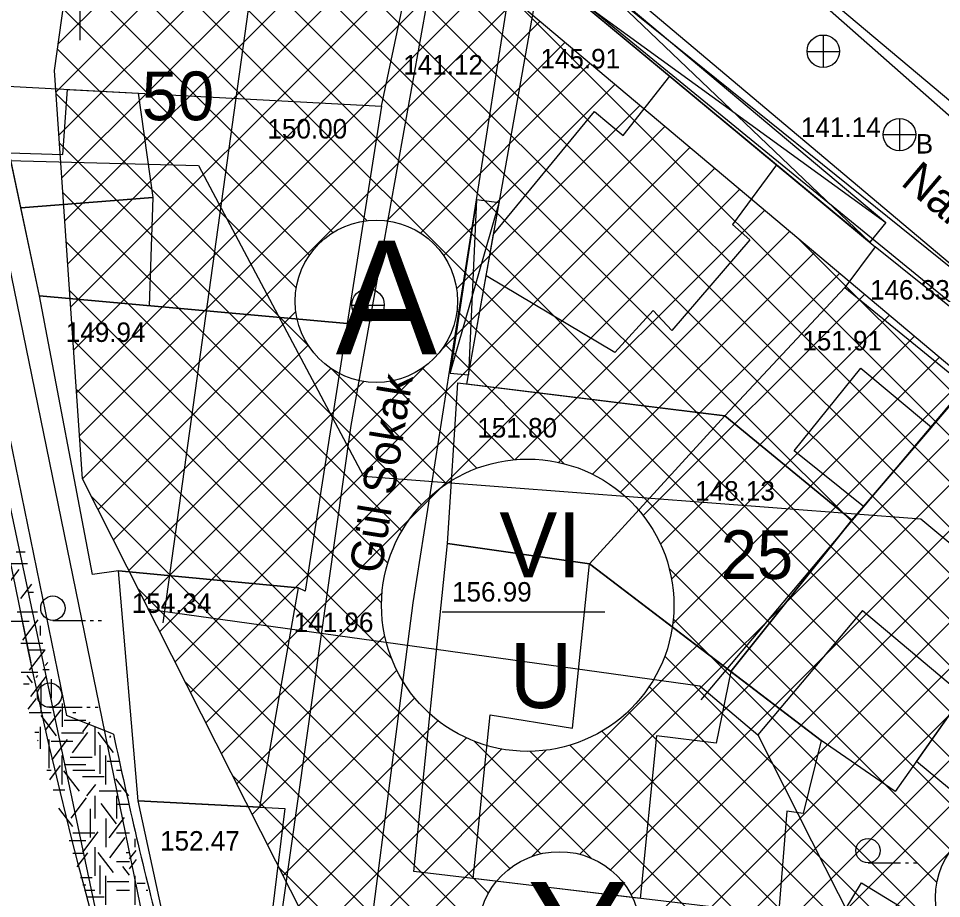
# Model space of a CAD drawing. Extents: x 419677 to 421689, y 4450851 to 4452923.
# Drawn here: x 420231.8 to 420288.6, y 4452130.4 to 4452184.6 of the extents above; entities that cross this region are included whole.
import ezdxf

# ---------------------------------------------------------------- set-up
doc = ezdxf.new("R2010")
doc.units = 0
for name, color, linetype in [('AA_HH', 7, 'Continuous'), ('Level 10', 7, 'Continuous'), ('Level 15', 7, 'Continuous'), ('Level 20', 7, 'Continuous'), ('Level 28', 7, 'Continuous'), ('Level 29', 7, 'Continuous'), ('Level 30', 7, 'Continuous'), ('Level 41', 7, 'Continuous'), ('Level 62', 7, 'Continuous')]:
    doc.layers.add(name, color=color, linetype=linetype)

msp = doc.modelspace()

# ---------------------------------------------------------------- linework, layer by layer
at = {"layer": 'AA_HH'}
for p, q in [((420266.416, 4452187.768), (420284.172, 4452170.798)), ((420265.363, 4452186.419), (420285.166, 4452172.017)), ((420235.533, 4452185.111), (420235.533, 4452183.236)), ((420281.324, 4452181.552), (420281.324, 4452183.552)), ((420280.304, 4452182.542), (420282.304, 4452182.542)), ((420286.001, 4452178.424), (420286.001, 4452176.424)), ((420285.001, 4452177.424), (420287.001, 4452177.424)), ((420259.952, 4452173.411), (420259.468, 4452162.634)), ((420258.338, 4452162.735), (420261.358, 4452173.232)), ((420253.301, 4452165.935), (420253.301, 4452167.935)), ((420252.281, 4452166.925), (420254.281, 4452166.925)), ((420233.881, 4452147.512), (420235.881, 4452147.512)), ((420236.181, 4452147.512), (420236.381, 4452147.512)), ((420236.681, 4452147.512), (420236.881, 4452147.512)), ((420233.677, 4452142.157), (420235.677, 4452142.157)), ((420235.977, 4452142.157), (420236.177, 4452142.157)), ((420236.477, 4452142.157), (420236.677, 4452142.157)), ((420284.066, 4452132.581), (420286.066, 4452132.581)), ((420286.366, 4452132.581), (420286.566, 4452132.581)), ((420286.866, 4452132.581), (420287.066, 4452132.581))]:
    msp.add_line(p, q, dxfattribs=at)
for points in [[(420352.944, 4452159.133), (420361.771, 4452152.879), (420362.386, 4452152.394), (420353.397, 4452135.521), (420352.686, 4452134.255), (420351.224, 4452132.128), (420350.275, 4452131.389), (420349.05, 4452130.978), (420327.85, 4452147.887), (420296.813, 4452171.753), (420266.296, 4452198.677), (420250.467, 4452210.766), (420249.861, 4452211.481), (420259.056, 4452228.461), (420259.243, 4452228.856), (420259.272, 4452228.855), (420283.37, 4452211.714), (420313.157, 4452188.272), (420343.707, 4452165.979), (420350.174, 4452161.23)], [(420254.116, 4452179.185), (420257.093, 4452193.267), (420247.74, 4452200.845), (420240.553, 4452190.955), (420239.958, 4452185.561), (420235.195, 4452186.019), (420235.496, 4452188.532), (420228.796, 4452188.104), (420230.305, 4452180.447)], [(420265.363, 4452186.419), (420266.416, 4452187.768), (420285.166, 4452172.017), (420284.172, 4452170.798)], [(420263.818, 4452187.028), (420263.951, 4452187.309), (420264.101, 4452187.467), (420284.502, 4452170.524), (420282.631, 4452168.005), (420275.258, 4452160.098), (420259.366, 4452162.062)], [(420278.437, 4452175.562), (420275.727, 4452171.888), (420276.781, 4452170.941), (420271.985, 4452165.357), (420270.84, 4452166.595), (420268.48, 4452163.997), (420260.555, 4452168.73), (420261.014, 4452171.301), (420267.22, 4452178.843), (420268.994, 4452177.374), (420271.861, 4452181.022)], [(420254.116, 4452179.185), (420251.995, 4452165.787), (420233.052, 4452167.49), (420230.305, 4452180.447)], [(420239.124, 4452179.979), (420240.033, 4452173.551), (420231.901, 4452172.92), (420231.182, 4452176.308), (420234.501, 4452176.195), (420234.775, 4452180.21)], [(420240.033, 4452173.551), (420239.812, 4452166.882), (420233.052, 4452167.49), (420231.901, 4452172.92)], [(420259.952, 4452173.411), (420258.338, 4452162.735), (420259.468, 4452162.634), (420261.358, 4452173.232)], [(420292.301, 4452164.262), (420284.502, 4452170.524), (420282.631, 4452168.005), (420275.258, 4452160.098), (420283.072, 4452153.686), (420290.11, 4452161.914)], [(420282.631, 4452168.005), (420290.11, 4452161.914), (420283.072, 4452153.686), (420275.258, 4452160.098)], [(420237.926, 4452150.567), (420236.324, 4452150.345), (420233.052, 4452167.49), (420251.995, 4452165.787), (420249.406, 4452149.308), (420248.991, 4452149.506)], [(420292.301, 4452164.262), (420300.187, 4452158.177), (420292.745, 4452146.898), (420285.741, 4452136.973), (420281.18, 4452140.104), (420275.613, 4452144.356), (420283.072, 4452153.686), (420290.11, 4452161.914), (420292.301, 4452164.262)], [(420283.616, 4452163.039), (420287.974, 4452159.417), (420283.782, 4452154.516), (420279.514, 4452157.957)], [(420258.808, 4452162.131), (420275.258, 4452160.098), (420266.921, 4452150.994), (420258.177, 4452152.252)], [(420275.613, 4452144.356), (420266.921, 4452150.994), (420275.258, 4452160.098), (420283.072, 4452153.686)], [(420258.177, 4452152.252), (420266.921, 4452150.994), (420281.18, 4452140.104), (420280.067, 4452135.62), (420279.068, 4452135.763), (420278.558, 4452129.368), (420256.096, 4452132.044)], [(420260.808, 4452141.69), (420265.865, 4452140.873), (420266.921, 4452150.994), (420275.613, 4452144.356), (420274.71, 4452139.957), (420271.048, 4452140.391), (420270.033, 4452130.383), (420259.764, 4452131.607)], [(420239.128, 4452136.395), (420237.926, 4452150.567), (420248.991, 4452149.506), (420246.593, 4452136.009)], [(420295.058, 4452132.188), (420287.043, 4452138.817), (420292.745, 4452146.898), (420300.695, 4452140.202)], [(420239.128, 4452136.395), (420248.167, 4452135.928), (420246.89, 4452125.545), (420242.757, 4452126.778), (420240.698, 4452129.198)], [(420283.654, 4452131.354), (420288.842, 4452128.191), (420284.002, 4452120.192), (420279.346, 4452124.232)]]:
    msp.add_lwpolyline(points, close=True, dxfattribs=at)
for points in [[(420218.584, 4452209.141), (420218.826, 4452220.645), (420219.181, 4452221.18), (420220.04, 4452222.122), (420221.518, 4452223.313), (420222.694, 4452223.784), (420223.995, 4452223.519), (420241.471, 4452208.64), (420258.365, 4452193.694), (420252.218, 4452159.511), (420247.093, 4452123.365)], [(420420.283, 4451972.04), (420421.029, 4451970.095), (420421.342, 4451968.715), (420420.96, 4451967.485), (420420.456, 4451967.019), (420419.682, 4451966.656), (420419.467, 4451966.604), (420419.102, 4451966.589), (420380.556, 4451986.723), (420357.561, 4451999.25), (420318.688, 4452023.585), (420304.823, 4452033.943), (420285.337, 4452050.002), (420272.264, 4452064.398), (420263.435, 4452076.857), (420254.665, 4452090.863), (420245.178, 4452107.602), (420239.444, 4452119.113), (420237.151, 4452126.743), (420229.958, 4452160.587), (420223.737, 4452191.2), (420219.459, 4452205.797)], [(420252.141, 4452118.284), (420256.069, 4452148.592), (420262.149, 4452187.413), (420262.61, 4452188.31), (420262.78, 4452188.76), (420263.144, 4452189.538), (420263.465, 4452189.953), (420295.785, 4452163.899), (420336.018, 4452130.364), (420340.603, 4452126.704), (420341.067, 4452126.076), (420341.172, 4452125.645), (420340.83, 4452124.652), (420326.41, 4452113.335), (420304.202, 4452097.602), (420273.848, 4452080.854)]]:
    msp.add_lwpolyline(points, dxfattribs=at)
for centre, radius in [((420281.309, 4452182.56), 1), ((420286.001, 4452177.424), 1), ((420253.286, 4452166.943), 1), ((420233.881, 4452148.262), 0.75), ((420233.677, 4452142.907), 0.75), ((420284.066, 4452133.331), 0.75)]:
    msp.add_circle(centre, radius, dxfattribs=at)
at = {"layer": 'Level 10'}
for points in [[(420307.877, 4452088.939), (420311.575, 4452102.803), (420341.372, 4452124.392), (420225.253, 4452219.297), (420221.566, 4452216.309), (420240.697, 4452122.918), (420266.112, 4452075.76), (420281.141, 4452057.098), (420289.665, 4452048.961)], [(420172.492, 4452177.283), (420195.149, 4452176.78), (420242.848, 4452175.53), (420253.006, 4452156.4), (420287.317, 4452153.757), (420313.693, 4452131.767), (420310.654, 4452111.087), (420327.406, 4452103.4), (420329.01, 4452096.964), (420314.753, 4452088.203), (420314.554, 4452087.519)]]:
    msp.add_lwpolyline(points, dxfattribs=at)
at = {"layer": 'Level 15'}
for p, q in [((420305.652, 4452131.003), (420237.695, 4452198.96)), ((420305.996, 4452133.487), (420240.98, 4452198.503)), ((420306.341, 4452135.971), (420244.265, 4452198.047)), ((420234.218, 4452183.016), (420248.528, 4452197.326)), ((420305.308, 4452128.519), (420236.243, 4452197.584)), ((420306.685, 4452138.455), (420247.55, 4452197.59)), ((420234.08, 4452180.05), (420250.064, 4452196.033)), ((420304.963, 4452126.035), (420235.898, 4452195.101)), ((420234.261, 4452177.403), (420251.6, 4452194.741)), ((420234.442, 4452174.755), (420253.136, 4452193.449)), ((420234.623, 4452172.108), (420254.673, 4452192.157)), ((420292.753, 4452135.417), (420235.553, 4452192.617)), ((420234.804, 4452169.46), (420256.209, 4452190.865)), ((420253.212, 4452172.129), (420235.207, 4452190.134)), ((420234.985, 4452166.813), (420257.745, 4452189.573)), ((420235.166, 4452164.165), (420259.281, 4452188.28)), ((420251.124, 4452171.389), (420234.862, 4452187.651)), ((420235.347, 4452161.518), (420260.817, 4452186.988)), ((420307.03, 4452140.939), (420261.845, 4452186.124)), ((420235.528, 4452158.87), (420262.354, 4452185.696)), ((420249.682, 4452170.002), (420234.517, 4452185.167)), ((420235.712, 4452156.226), (420263.89, 4452184.404)), ((420254.437, 4452172.122), (420265.426, 4452183.112)), ((420248.866, 4452167.99), (420234.172, 4452182.684)), ((420256.507, 4452171.365), (420266.962, 4452181.819)), ((420257.938, 4452169.966), (420268.499, 4452180.527)), ((420249.633, 4452164.395), (420234.088, 4452179.94)), ((420258.737, 4452167.937), (420270.035, 4452179.235)), ((420257.865, 4452164.237), (420271.571, 4452177.943)), ((420256.575, 4452154.624), (420234.295, 4452176.904)), ((420241.409, 4452144.952), (420273.107, 4452176.651)), ((420242.358, 4452143.073), (420274.644, 4452175.359)), ((420243.308, 4452141.194), (420276.18, 4452174.066)), ((420255.362, 4452153.01), (420234.503, 4452173.868)), ((420262.351, 4452157.409), (420277.716, 4452172.774)), ((420265.01, 4452157.24), (420279.252, 4452171.482)), ((420307.374, 4452143.423), (420279.648, 4452171.149)), ((420254.5, 4452151.042), (420234.71, 4452170.832)), ((420267.107, 4452156.508), (420280.789, 4452170.19)), ((420268.826, 4452155.399), (420282.325, 4452168.898)), ((420254.117, 4452148.597), (420234.918, 4452167.796)), ((420270.222, 4452153.966), (420283.861, 4452167.605)), ((420236.662, 4452154.347), (420248.838, 4452166.524)), ((420290.627, 4452134.714), (420258.763, 4452166.578)), ((420271.291, 4452152.207), (420285.397, 4452166.313)), ((420271.97, 4452150.057), (420286.934, 4452165.021)), ((420254.743, 4452145.142), (420235.125, 4452164.76)), ((420237.611, 4452152.468), (420249.595, 4452164.452)), ((420265.354, 4452157.159), (420258.023, 4452164.49)), ((420272.044, 4452147.303), (420288.47, 4452163.729)), ((420240.459, 4452146.831), (420256.773, 4452163.145)), ((420238.56, 4452150.589), (420250.994, 4452163.023)), ((420258.108, 4452155.92), (420251.029, 4452162.999)), ((420262.281, 4452157.403), (420256.636, 4452163.048)), ((420239.51, 4452148.71), (420253.023, 4452162.223)), ((420251.852, 4452124.283), (420290.006, 4452162.437)), ((420259.979, 4452156.877), (420254.624, 4452162.232)), ((420263.922, 4452133.134), (420235.333, 4452161.724)), ((420263.367, 4452132.97), (420291.542, 4452161.145)), ((420266.329, 4452133.102), (420293.079, 4452159.852)), ((420262.005, 4452132.223), (420235.54, 4452158.688)), ((420268.208, 4452132.152), (420294.615, 4452158.56)), ((420269.483, 4452130.6), (420296.151, 4452157.268)), ((420270.06, 4452128.349), (420297.687, 4452155.976)), ((420260.696, 4452130.704), (420236.261, 4452155.139)), ((420257.549, 4452113.009), (420299.224, 4452154.684)), ((420258.498, 4452111.13), (420300.76, 4452153.391)), ((420259.448, 4452109.251), (420302.296, 4452152.099)), ((420260.397, 4452107.372), (420303.832, 4452150.807)), ((420289.159, 4452133.354), (420271.833, 4452150.68)), ((420260.067, 4452128.505), (420239.15, 4452149.422)), ((420244.257, 4452139.315), (420254.149, 4452149.207)), ((420288.309, 4452131.375), (420272.077, 4452147.607)), ((420245.206, 4452137.436), (420254.318, 4452146.548)), ((420288.857, 4452127.999), (420271.551, 4452145.305)), ((420246.156, 4452135.557), (420255.05, 4452144.451)), ((420288.015, 4452097.729), (420242.039, 4452143.704)), ((420302.897, 4452111.131), (420270.594, 4452143.434)), ((420247.105, 4452133.678), (420256.159, 4452142.732)), ((420302.552, 4452108.647), (420269.298, 4452141.901)), ((420248.055, 4452131.799), (420257.592, 4452141.336)), ((420302.208, 4452106.163), (420267.684, 4452140.687)), ((420249.004, 4452129.92), (420259.351, 4452140.267)), ((420267.02, 4452132.866), (420259.818, 4452140.068)), ((420301.863, 4452103.679), (420265.716, 4452139.826)), ((420249.954, 4452128.041), (420261.501, 4452139.588)), ((420250.903, 4452126.162), (420264.255, 4452139.514)), ((420301.519, 4452101.195), (420263.271, 4452139.443)), ((420285.17, 4452097.745), (420244.928, 4452137.987)), ((420261.347, 4452105.493), (420289.698, 4452133.844)), ((420281.884, 4452098.202), (420247.817, 4452132.27))]:
    msp.add_line(p, q, dxfattribs=at)
at = {"layer": 'Level 20'}
for p, q in [((420247.785, 4452198.626), (420240.659, 4452147.352)), ((420290.716, 4452162.758), (420273.773, 4452142.612)), ((420239.772, 4452148.192), (420273.712, 4452143.475)), ((420283.721, 4452148.122), (420277.285, 4452140.47)), ((420283.721, 4452148.122), (420305.487, 4452129.814)), ((420273.712, 4452143.475), (420277.285, 4452140.47)), ((420277.285, 4452140.47), (420292.651, 4452110.059))]:
    msp.add_line(p, q, dxfattribs=at)
at = {"layer": 'Level 28'}
msp.add_lwpolyline([(420235.708, 4452156.234), (420233.99, 4452181.374), (420236.458, 4452199.132)], dxfattribs=at)
at = {"layer": 'Level 29'}
msp.add_line((420263.757, 4452100.723), (420235.708, 4452156.234), dxfattribs=at)
msp.add_lwpolyline([(420236.458, 4452199.132), (420248.344, 4452197.48), (420307.921, 4452147.368)], dxfattribs=at)
at = {"layer": 'Level 30'}
msp.add_line((420267.858, 4452148.023), (420257.858, 4452148.023), dxfattribs=at)
for centre, radius in [((420253.797, 4452167.163), 5), ((420263.116, 4452148.442), 9), ((420293.221, 4452130.439), 5), ((420265.061, 4452128.266), 5)]:
    msp.add_circle(centre, radius, dxfattribs=at)
at = {"layer": 'Level 41'}
for p, q in [((420231.622, 4452151.726), (420232.176, 4452151.726)), ((420230.927, 4452149.482), (420231.803, 4452150.635)), ((420231.089, 4452151.006), (420232.323, 4452151.006)), ((420231.92, 4452148.86), (420232.583, 4452149.733)), ((420232.432, 4452149.238), (420232.684, 4452149.238)), ((420231.676, 4452148.031), (420232.93, 4452148.031)), ((420231.317, 4452147.471), (420232.432, 4452147.471)), ((420232.025, 4452146.301), (420232.975, 4452147.551)), ((420233.104, 4452147.178), (420233.104, 4452146.588)), ((420231.915, 4452146.105), (420233.258, 4452146.105)), ((420232.432, 4452145.704), (420233.405, 4452145.704)), ((420232.451, 4452144.444), (420233.4, 4452145.693)), ((420233.411, 4452144.723), (420233.564, 4452144.924)), ((420233.274, 4452144.492), (420233.652, 4452144.492)), ((420231.928, 4452144.317), (420232.965, 4452144.317)), ((420232.638, 4452143.659), (420232.294, 4452144.111)), ((420232.531, 4452142.817), (420233.481, 4452144.067)), ((420232.864, 4452143.991), (420232.955, 4452144.111)), ((420233.775, 4452143.889), (420233.775, 4452142.713)), ((420232.067, 4452143.597), (420232.432, 4452143.597)), ((420233.131, 4452143.644), (420233.131, 4452141.877)), ((420232.368, 4452142.041), (420232.869, 4452142.701)), ((420234.447, 4452142.399), (420234.447, 4452140.946)), ((420232.432, 4452141.829), (420233.775, 4452141.829)), ((420234.103, 4452140.4), (420233.153, 4452141.649)), ((420233.437, 4452140.75), (420234.388, 4452141.999)), ((420235.118, 4452141.829), (420235.303, 4452141.829)), ((420233.104, 4452140.946), (420233.104, 4452139.596)), ((420234.578, 4452141.359), (420235.921, 4452141.359)), ((420235.728, 4452140.645), (420236.182, 4452141.243)), ((420236.461, 4452140.946), (420236.461, 4452139.179)), ((420232.781, 4452140.622), (420233.019, 4452140.622)), ((420234.418, 4452140.589), (420235.761, 4452140.589)), ((420235.088, 4452139.348), (420236.038, 4452140.598)), ((420237.618, 4452139.382), (420236.669, 4452140.631)), ((420237.379, 4452140.294), (420237.452, 4452140.39)), ((420232.945, 4452140.102), (420232.975, 4452140.142)), ((420233.636, 4452140.174), (420233.636, 4452138.406)), ((420233.775, 4452140.062), (420235.118, 4452140.062)), ((420233.836, 4452138.928), (420234.785, 4452140.177)), ((420236.779, 4452139.824), (420236.779, 4452138.056)), ((420234.447, 4452137.411), (420234.447, 4452139.179)), ((420234.952, 4452139.081), (420236.295, 4452139.081)), ((420237.133, 4452137.411), (420237.133, 4452139.179)), ((420237.215, 4452138.836), (420237.943, 4452138.836)), ((420233.513, 4452138.295), (420233.775, 4452138.295)), ((420233.701, 4452137.696), (420234.36, 4452138.564)), ((420235.514, 4452137), (420234.564, 4452138.249)), ((420234.578, 4452138.625), (420235.921, 4452138.625)), ((420235.118, 4452138.295), (420236.461, 4452138.295)), ((420237.804, 4452138.295), (420238.114, 4452138.295)), ((420235.697, 4452137.888), (420237.04, 4452137.888)), ((420238.563, 4452136.702), (420237.761, 4452137.758)), ((420233.894, 4452137.083), (420234.617, 4452137.083)), ((420235.98, 4452136.702), (420236.517, 4452137.408)), ((420236.736, 4452137.014), (420238.079, 4452137.014)), ((420235.008, 4452135.339), (420235.957, 4452136.589)), ((420236.461, 4452136.702), (420236.461, 4452135.304)), ((420237.804, 4452136.702), (420237.804, 4452135.304)), ((420237.804, 4452136.702), (420237.804, 4452135.304)), ((420235.115, 4452134.813), (420234.249, 4452135.953)), ((420236.179, 4452135.914), (420236.179, 4452134.147)), ((420237.805, 4452134.988), (420236.856, 4452136.237)), ((420237.804, 4452136.188), (420238.592, 4452136.188)), ((420237.133, 4452135.304), (420237.133, 4452133.537)), ((420237.133, 4452135.304), (420237.133, 4452133.537)), ((420237.353, 4452134.111), (420238.302, 4452135.361)), ((420235.118, 4452134.42), (420236.461, 4452134.42)), ((420235.728, 4452133.236), (420236.677, 4452134.486)), ((420237.379, 4452132.885), (420238.329, 4452134.134)), ((420237.804, 4452134.42), (420238.592, 4452134.42)), ((420234.878, 4452133.95), (420235.921, 4452133.95)), ((420238.954, 4452133.537), (420238.954, 4452134.055)), ((420235.116, 4452133.18), (420235.761, 4452133.18)), ((420235.38, 4452132.323), (420236.038, 4452133.189)), ((420236.461, 4452133.537), (420236.461, 4452131.77)), ((420237.618, 4452131.973), (420236.669, 4452133.222)), ((420238.388, 4452133.213), (420238.592, 4452133.213)), ((420238.602, 4452132.816), (420239.001, 4452133.342)), ((420237.804, 4452132.653), (420238.592, 4452132.653)), ((420238.592, 4452132.207), (420239.038, 4452132.794)), ((420236.779, 4452132.415), (420236.779, 4452130.647)), ((420238.592, 4452131.813), (420238.186, 4452132.347)), ((420235.58, 4452131.672), (420236.295, 4452131.672)), ((420237.133, 4452130.002), (420237.133, 4452131.77)), ((420237.215, 4452131.427), (420238.558, 4452131.427)), ((420238.954, 4452130.002), (420238.954, 4452131.77)), ((420239.077, 4452131.321), (420239.557, 4452131.321)), ((420235.721, 4452131.216), (420235.921, 4452131.216)), ((420235.822, 4452130.886), (420236.461, 4452130.886)), ((420237.804, 4452130.886), (420238.592, 4452130.886)), ((420239.625, 4452130.886), (420239.726, 4452130.886)), ((420235.947, 4452130.479), (420237.04, 4452130.479))]:
    msp.add_line(p, q, dxfattribs=at)
at = {"layer": 'Level 62'}
for p, q in [((420315.357, 4452147.315), (420227.832, 4452221.196)), ((420220.131, 4452205.443), (420232.517, 4452144.902)), ((420222.866, 4452199.549), (420234.715, 4452141.643)), ((420237.619, 4452140.494), (420234.715, 4452141.643))]:
    msp.add_line(p, q, dxfattribs=at)
msp.add_lwpolyline([(420341.086, 4452135.823), (420241.354, 4452219.63), (420230.181, 4452233.933)], dxfattribs=at)
for centre, radius, start, end in [((420509.913, 4452203.553), 283.529, 191.1934, 210.35878), ((420513.586, 4452198.651), 282.029, 191.90038, 194.55127), ((420509.913, 4452203.553), 290.529, 193.40687, 211.16796)]:
    msp.add_arc(centre, radius, start, end, dxfattribs=at)

# ---------------------------------------------------------------- texts
at = {"layer": 'AA_HH'}
for s, p in [('145.91', (420263.895, 4452181.503)), ('150.00 ', (420247.09, 4452177.186)), ('B', (420287.001, 4452176.262)), ('146.33', (420284.187, 4452167.267)), ('149.94', (420234.679, 4452164.658)), ('151.91', (420280.02, 4452164.138)), ('151.80', (420260.011, 4452158.771)), ('148.13', (420273.422, 4452154.885)), ('156.99', (420258.453, 4452148.668)), ('154.34', (420238.74, 4452147.969)), ('152.47', (420240.481, 4452133.333))]:
    msp.add_text(s, height=1.2, dxfattribs=at).set_placement(p)
for s, height, rotation, p in [('141.12 ', 1.2, 0.0026, (420255.452, 4452181.126)), ('141.14 ', 1.2, 0.0026, (420279.933, 4452177.28)), ('Nane  Sokak', 2, 319.7819, (420286.012, 4452174.384)), ('Gül Sokak', 2, 80.8281, (420254.094, 4452150.325)), ('141.96 ', 1.2, 0.0026, (420248.709, 4452146.794))]:
    msp.add_text(s, height=height, rotation=rotation, dxfattribs=at).set_placement(p)
at = {"layer": 'Level 20'}
for s, p in [('50', (420239.352, 4452178.31)), ('25', (420274.994, 4452150.06))]:
    msp.add_text(s, height=3, dxfattribs=at).set_placement(p)
at = {"layer": 'Level 30'}
for s, height, p in [('A', 7, (420251.292, 4452163.897)), ('VI', 4, (420261.368, 4452150.163)), ('U', 4, (420262.006, 4452142.113)), ('Y', 7, (420263.081, 4452124.392))]:
    msp.add_text(s, height=height, dxfattribs=at).set_placement(p)

doc.saveas('drawing.dxf')
